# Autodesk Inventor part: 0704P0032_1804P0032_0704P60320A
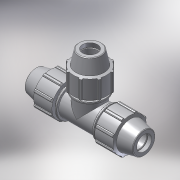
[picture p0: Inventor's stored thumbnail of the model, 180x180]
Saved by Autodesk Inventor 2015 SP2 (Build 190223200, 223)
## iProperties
Created: 2017-02
Part Number: 0704P0032_1804P0032_0704P60320A
Material: PVC-Piping
Description: PLASSON REPAIR TEE 32
Document SubType Name: Modeling
Designer: KIM
Mass: 92.6774 g
Surface Area: 199.44 cm^2
Volume: 66.1981 cm^3
Density: 1.4 g/cm^3
Appearance: Smooth - White
Author: Кирилл
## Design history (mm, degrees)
derived "0704P0.ipt"
feature "Solid1::0704P0.ipt"
tag "TaggingFeature1"
body "Solid1"
other parameters: "d2" = 32, "d4" = 7.75, "d5" = 23.25, "d7" = 64, "d11" = 3.1, "d13" = 120 deg, "d14" = 48, "d15" = 12 deg, "d16" = 55.68, "d18" = 1.6, "d19" = 35 deg, "d20" = 17.5 deg, "d21" = 59.52, "d23" = 0, "d25" = 360 deg, "d27" = 1.28, "d33" = 0.64, "d42" = 32.55, "d43" = 1.92, "d46" = 0.96, "d63" = 67, "d67" = 48, "d76" = 32, "d77" = 64, "d78" = 12 deg, "d79" = 93, "d80" = 120 deg, "d81" = 48, "d82" = 7.75, "d85" = 48, "d86" = 55.68, "d87" = 3.1, "d88" = 3.1, "d89" = 23.25, "d90" = 32.55, "d96" = 4.65, "d98" = 59.52, "d99" = 35 deg, "d100" = 17.5 deg, "d102" = 0, "d103" = 1.28, "d107" = 360 deg, "d109" = 0.96, "d112" = 1.6, "d118" = 360 deg, "d121" = 0, "d128" = 185, "d131" = 28.8, "d132" = 28.8, "d133" = 67, "d134" = 1.34, "d135" = 4.65, "d152" = 0, "d154" = 0, "d156" = 0, "d158" = 0, "d_" = 32, "E_" = 64, "A_" = 93, "l_" = 67, "H_" = 185
